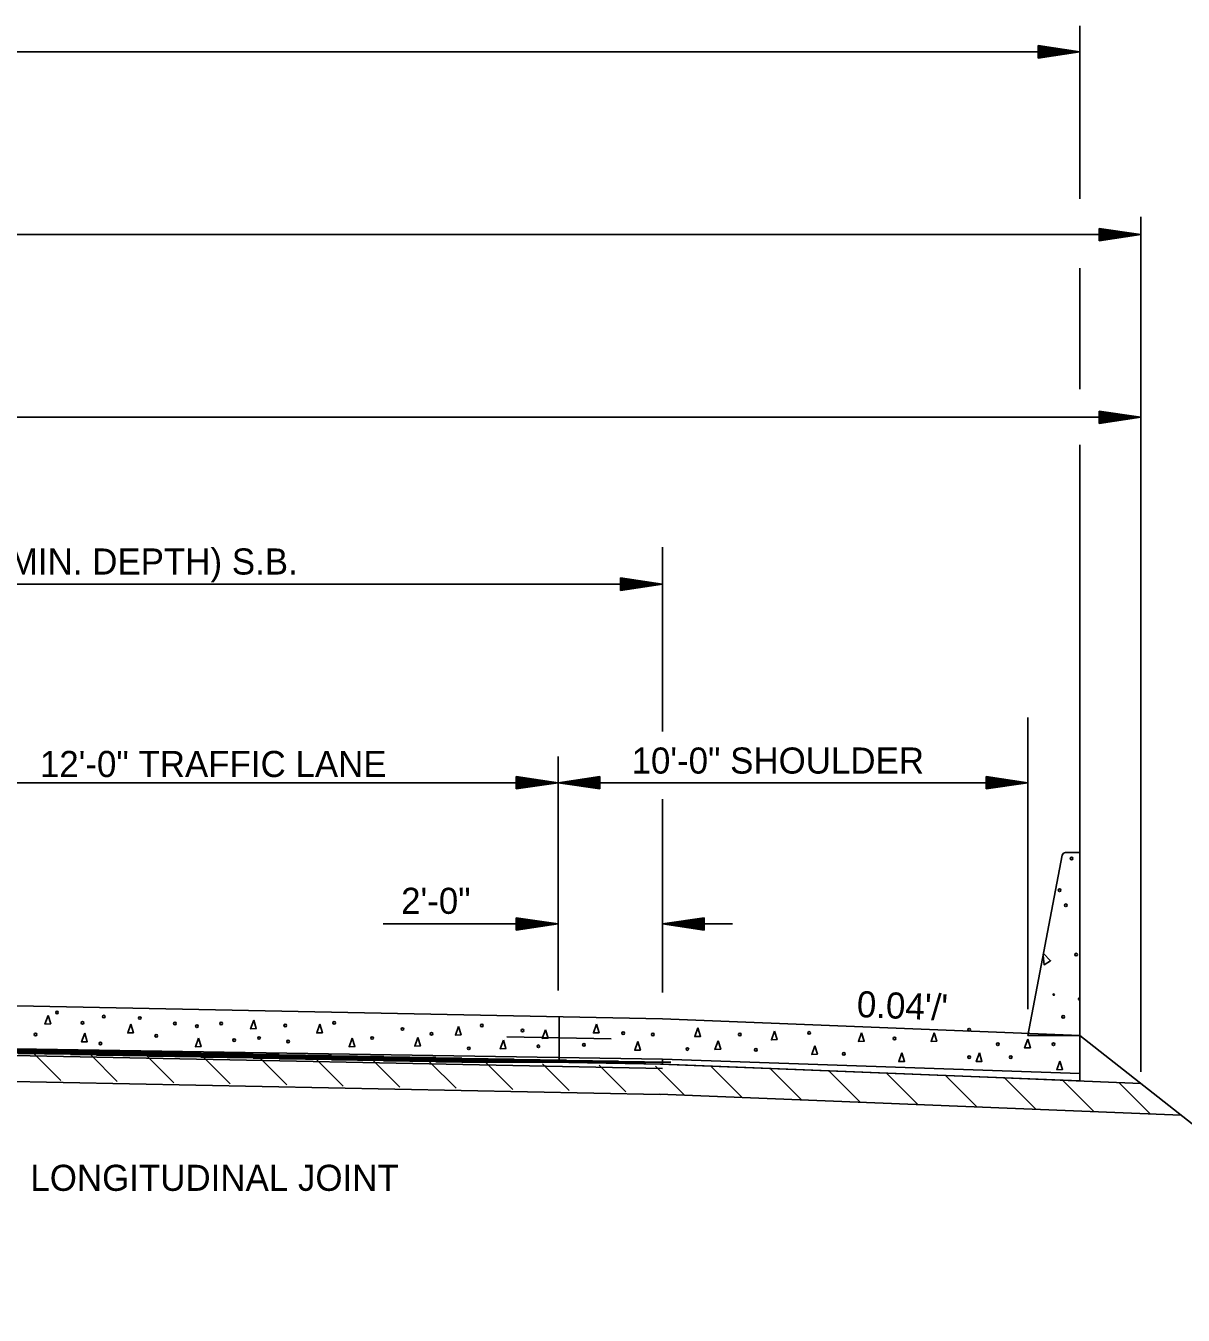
# Model space of a CAD drawing. Extents: x 60325 to 61047, y 53669 to 53767.
# Drawn here: x 60598.35 to 60620.52, y 53687.92 to 53712.62 of the extents above; entities that cross this region are included whole.
import ezdxf

# ---------------------------------------------------------------- set-up
doc = ezdxf.new("R2010")
doc.units = 0
doc.layers.add('R_Border', color=7, linetype='Continuous')
doc.layers.add('R_Border Prem', color=7, linetype='Continuous')

msp = doc.modelspace()

# ---------------------------------------------------------------- linework, layer by layer
at = {"layer": 'R_Border'}
for p, q in [((60610.545, 53699.103), (60610.545, 53702.635)), ((60610.545, 53701.929), (60582.545, 53701.929)), ((60609.745, 53702.049), (60610.545, 53701.929)), ((60609.745, 53702.049), (60609.745, 53701.809)), ((60609.745, 53702.029), (60610.412, 53701.929)), ((60609.745, 53702.009), (60610.274, 53701.929)), ((60609.745, 53701.989), (60610.141, 53701.929)), ((60609.745, 53701.968), (60610.005, 53701.929)), ((60609.745, 53701.948), (60609.872, 53701.929)), ((60609.745, 53701.809), (60610.545, 53701.929)), ((60609.745, 53701.89), (60610.005, 53701.929)), ((60609.745, 53701.85), (60610.274, 53701.929)), ((60609.745, 53701.829), (60610.412, 53701.929)), ((60609.745, 53701.87), (60610.141, 53701.929)), ((60609.745, 53701.911), (60609.872, 53701.929)), ((60608.545, 53694.144), (60608.545, 53698.624)), ((60607.745, 53698.244), (60608.545, 53698.124)), ((60607.745, 53698.244), (60607.745, 53698.004)), ((60607.745, 53698.224), (60608.412, 53698.124)), ((60608.545, 53698.124), (60596.545, 53698.124)), ((60607.745, 53698.204), (60608.274, 53698.124)), ((60607.745, 53698.184), (60608.141, 53698.124)), ((60607.745, 53698.163), (60608.005, 53698.124)), ((60607.745, 53698.143), (60607.872, 53698.124)), ((60607.745, 53698.004), (60608.545, 53698.124)), ((60607.745, 53698.085), (60608.005, 53698.124)), ((60607.745, 53698.045), (60608.274, 53698.124)), ((60607.745, 53698.024), (60608.412, 53698.124)), ((60607.745, 53698.065), (60608.141, 53698.124)), ((60607.745, 53698.106), (60607.872, 53698.124)), ((60610.545, 53694.104), (60610.545, 53697.812)), ((60607.745, 53695.538), (60608.545, 53695.418)), ((60607.745, 53695.298), (60607.745, 53695.538)), ((60607.745, 53695.518), (60608.412, 53695.418)), ((60611.345, 53695.538), (60610.545, 53695.418)), ((60611.345, 53695.518), (60610.679, 53695.418)), ((60611.345, 53695.538), (60611.345, 53695.298)), ((60605.198, 53695.418), (60608.545, 53695.418)), ((60607.745, 53695.498), (60608.274, 53695.418)), ((60607.745, 53695.478), (60608.141, 53695.418)), ((60607.745, 53695.458), (60608.005, 53695.418)), ((60607.745, 53695.437), (60607.872, 53695.418)), ((60607.745, 53695.298), (60608.545, 53695.418)), ((60607.745, 53695.38), (60608.005, 53695.418)), ((60607.745, 53695.339), (60608.274, 53695.418)), ((60607.745, 53695.318), (60608.412, 53695.418)), ((60607.745, 53695.359), (60608.141, 53695.418)), ((60607.745, 53695.4), (60607.872, 53695.418)), ((60610.545, 53695.418), (60611.887, 53695.418)), ((60611.345, 53695.298), (60610.545, 53695.418)), ((60611.345, 53695.318), (60610.679, 53695.418)), ((60611.345, 53695.498), (60610.816, 53695.418)), ((60611.345, 53695.339), (60610.816, 53695.418)), ((60611.345, 53695.478), (60610.95, 53695.418)), ((60611.345, 53695.359), (60610.95, 53695.418)), ((60611.345, 53695.457), (60611.085, 53695.418)), ((60611.345, 53695.379), (60611.085, 53695.418)), ((60611.345, 53695.437), (60611.219, 53695.418)), ((60611.345, 53695.4), (60611.219, 53695.418)), ((60608.564, 53693.655), (60608.564, 53692.822)), ((60607.564, 53693.259), (60608.564, 53693.239)), ((60608.564, 53693.239), (60609.564, 53693.219))]:
    msp.add_line(p, q, dxfattribs=at)
msp.add_lwpolyline([(60582.532, 53694.162), (60584.53, 53694.125), (60610.545, 53693.604)], dxfattribs=at)
at = {"layer": 'R_Border Prem'}
for p, q in [((60618.545, 53709.307), (60618.545, 53712.624)), ((60618.545, 53712.124), (60524.545, 53712.124)), ((60617.745, 53712.244), (60618.545, 53712.124)), ((60617.745, 53712.244), (60617.745, 53712.004)), ((60617.745, 53712.224), (60618.412, 53712.124)), ((60617.745, 53712.204), (60618.274, 53712.124)), ((60617.745, 53712.184), (60618.141, 53712.124)), ((60617.745, 53712.163), (60618.005, 53712.124)), ((60617.745, 53712.143), (60617.872, 53712.124)), ((60617.745, 53712.004), (60618.545, 53712.124)), ((60617.745, 53712.085), (60618.005, 53712.124)), ((60617.745, 53712.045), (60618.274, 53712.124)), ((60617.745, 53712.024), (60618.412, 53712.124)), ((60617.745, 53712.065), (60618.141, 53712.124)), ((60617.745, 53712.106), (60617.872, 53712.124)), ((60619.713, 53696.197), (60619.713, 53708.966)), ((60619.713, 53708.624), (60522.149, 53708.624)), ((60618.913, 53708.744), (60619.713, 53708.624)), ((60618.913, 53708.744), (60618.913, 53708.504)), ((60618.913, 53708.724), (60619.58, 53708.624)), ((60618.913, 53708.704), (60619.442, 53708.624)), ((60618.913, 53708.684), (60619.309, 53708.624)), ((60618.913, 53708.663), (60619.173, 53708.624)), ((60618.913, 53708.643), (60619.04, 53708.624)), ((60618.913, 53708.504), (60619.713, 53708.624)), ((60618.913, 53708.585), (60619.173, 53708.624)), ((60618.913, 53708.545), (60619.442, 53708.624)), ((60618.913, 53708.524), (60619.58, 53708.624)), ((60618.913, 53708.565), (60619.309, 53708.624)), ((60618.913, 53708.606), (60619.04, 53708.624)), ((60618.545, 53705.666), (60618.545, 53707.983)), ((60618.913, 53705.244), (60619.713, 53705.124)), ((60618.913, 53705.244), (60618.913, 53705.004)), ((60618.913, 53705.224), (60619.58, 53705.124)), ((60618.913, 53705.204), (60619.442, 53705.124)), ((60618.913, 53705.184), (60619.309, 53705.124)), ((60618.913, 53705.163), (60619.173, 53705.124)), ((60618.913, 53705.143), (60619.04, 53705.124)), ((60619.713, 53705.124), (60522.149, 53705.124)), ((60618.913, 53705.004), (60619.713, 53705.124)), ((60618.913, 53705.085), (60619.173, 53705.124)), ((60618.913, 53705.045), (60619.442, 53705.124)), ((60618.913, 53705.024), (60619.58, 53705.124)), ((60618.913, 53705.065), (60619.309, 53705.124)), ((60618.913, 53705.106), (60619.04, 53705.124)), ((60618.545, 53696.785), (60618.545, 53704.599)), ((60617.549, 53693.784), (60617.549, 53699.374)), ((60609.345, 53698.244), (60608.545, 53698.124)), ((60609.345, 53698.224), (60608.679, 53698.124)), ((60609.345, 53698.004), (60609.345, 53698.244)), ((60616.749, 53698.244), (60617.549, 53698.124)), ((60616.749, 53698.244), (60616.749, 53698.004)), ((60616.749, 53698.224), (60617.416, 53698.124)), ((60617.549, 53698.124), (60608.545, 53698.124)), ((60609.345, 53698.004), (60608.545, 53698.124)), ((60609.345, 53698.024), (60608.679, 53698.124)), ((60609.345, 53698.204), (60608.816, 53698.124)), ((60609.345, 53698.045), (60608.816, 53698.124)), ((60609.345, 53698.184), (60608.95, 53698.124)), ((60609.345, 53698.065), (60608.95, 53698.124)), ((60609.345, 53698.164), (60609.085, 53698.124)), ((60609.345, 53698.086), (60609.085, 53698.124)), ((60609.345, 53698.143), (60609.219, 53698.124)), ((60609.345, 53698.106), (60609.219, 53698.124)), ((60616.749, 53698.204), (60617.278, 53698.124)), ((60616.749, 53698.184), (60617.145, 53698.124)), ((60616.749, 53698.163), (60617.009, 53698.124)), ((60616.749, 53698.143), (60616.876, 53698.124)), ((60616.749, 53698.004), (60617.549, 53698.124)), ((60616.749, 53698.085), (60617.009, 53698.124)), ((60616.749, 53698.045), (60617.278, 53698.124)), ((60616.749, 53698.024), (60617.416, 53698.124)), ((60616.749, 53698.065), (60617.145, 53698.124)), ((60616.749, 53698.106), (60616.876, 53698.124)), ((60618.208, 53696.738), (60617.549, 53693.284)), ((60618.546, 53696.785), (60618.268, 53696.785)), ((60618.545, 53693.284), (60618.546, 53696.785)), ((60619.713, 53692.586), (60619.713, 53696.197)), ((60618.545, 53693.784), (60618.545, 53692.411)), ((60610.545, 53693.604), (60618.545, 53693.284)), ((60571.545, 53693.511), (60610.545, 53692.731)), ((60571.545, 53693.431), (60610.545, 53692.651)), ((60617.549, 53693.284), (60618.545, 53693.284)), ((60618.545, 53693.284), (60625.351, 53687.924)), ((60571.545, 53692.931), (60610.502, 53692.152)), ((60594.704, 53693.008), (60598.705, 53693.008)), ((60595.204, 53692.998), (60599.205, 53692.998)), ((60595.704, 53692.988), (60599.705, 53692.988)), ((60596.204, 53692.978), (60600.205, 53692.978)), ((60596.704, 53692.968), (60600.705, 53692.968)), ((60597.204, 53692.958), (60601.205, 53692.958)), ((60597.704, 53692.948), (60601.705, 53692.948)), ((60598.204, 53692.938), (60602.205, 53692.938)), ((60598.508, 53692.932), (60599.019, 53692.421)), ((60598.704, 53692.928), (60602.705, 53692.928)), ((60599.204, 53692.918), (60603.205, 53692.918)), ((60599.591, 53692.91), (60600.101, 53692.4)), ((60599.704, 53692.908), (60603.705, 53692.908)), ((60600.204, 53692.898), (60604.205, 53692.898)), ((60600.673, 53692.888), (60601.183, 53692.378)), ((60600.704, 53692.888), (60604.705, 53692.888)), ((60601.204, 53692.878), (60605.205, 53692.878)), ((60601.704, 53692.868), (60605.705, 53692.868)), ((60601.755, 53692.867), (60602.266, 53692.356)), ((60602.204, 53692.858), (60606.205, 53692.858)), ((60602.704, 53692.848), (60606.705, 53692.848)), ((60602.838, 53692.845), (60603.348, 53692.335)), ((60603.204, 53692.838), (60607.205, 53692.838)), ((60603.704, 53692.828), (60607.705, 53692.828)), ((60603.92, 53692.823), (60604.43, 53692.313)), ((60604.204, 53692.818), (60608.205, 53692.818)), ((60604.704, 53692.808), (60608.705, 53692.808)), ((60605.002, 53692.802), (60605.513, 53692.292)), ((60605.204, 53692.798), (60609.205, 53692.798)), ((60605.704, 53692.788), (60609.705, 53692.788)), ((60606.085, 53692.78), (60606.595, 53692.27)), ((60606.204, 53692.778), (60610.205, 53692.778)), ((60606.704, 53692.768), (60610.705, 53692.768)), ((60607.167, 53692.759), (60607.677, 53692.248)), ((60608.249, 53692.737), (60608.759, 53692.227)), ((60609.331, 53692.715), (60609.842, 53692.205)), ((60610.414, 53692.694), (60610.97, 53692.137)), ((60610.51, 53692.732), (60618.545, 53692.411)), ((60611.474, 53692.694), (60612.075, 53692.093)), ((60612.613, 53692.648), (60613.213, 53692.048)), ((60613.735, 53692.603), (60614.336, 53692.003)), ((60614.838, 53692.559), (60615.438, 53691.959)), ((60615.968, 53692.514), (60616.568, 53691.914)), ((60617.078, 53692.47), (60619.713, 53692.364)), ((60617.098, 53692.469), (60617.698, 53691.868)), ((60618.21, 53692.424), (60618.811, 53691.824)), ((60619.293, 53692.381), (60619.894, 53691.781)), ((60610.487, 53692.157), (60620.484, 53691.757))]:
    msp.add_line(p, q, dxfattribs=at)
for points in [[(60617.841, 53694.813), (60617.858, 53694.636), (60617.983, 53694.714), (60617.848, 53694.85)], [(60598.776, 53693.668), (60598.715, 53693.502), (60598.825, 53693.506), (60598.776, 53693.668)], [(60602.714, 53693.575), (60602.653, 53693.409), (60602.763, 53693.414), (60602.714, 53693.575)], [(60599.476, 53693.324), (60599.416, 53693.158), (60599.526, 53693.163), (60599.476, 53693.324)], [(60600.362, 53693.496), (60600.301, 53693.33), (60600.411, 53693.334), (60600.362, 53693.496)], [(60603.983, 53693.496), (60603.922, 53693.33), (60604.032, 53693.334), (60603.983, 53693.496)], [(60606.639, 53693.456), (60606.579, 53693.29), (60606.689, 53693.295), (60606.639, 53693.456)], [(60608.304, 53693.39), (60608.244, 53693.224), (60608.354, 53693.229), (60608.304, 53693.39)], [(60609.282, 53693.496), (60609.222, 53693.33), (60609.332, 53693.334), (60609.282, 53693.496)], [(60611.227, 53693.426), (60611.166, 53693.26), (60611.276, 53693.265), (60611.227, 53693.426)], [(60612.694, 53693.364), (60612.634, 53693.198), (60612.744, 53693.203), (60612.694, 53693.364)], [(60614.363, 53693.333), (60614.302, 53693.167), (60614.412, 53693.172), (60614.363, 53693.333)], [(60615.753, 53693.333), (60615.693, 53693.167), (60615.803, 53693.172), (60615.753, 53693.333)], [(60601.657, 53693.232), (60601.596, 53693.066), (60601.706, 53693.07), (60601.657, 53693.232)], [(60604.604, 53693.232), (60604.543, 53693.066), (60604.653, 53693.07), (60604.604, 53693.232)], [(60605.859, 53693.245), (60605.799, 53693.079), (60605.909, 53693.083), (60605.859, 53693.245)], [(60607.498, 53693.192), (60607.438, 53693.026), (60607.548, 53693.03), (60607.498, 53693.192)], [(60610.075, 53693.166), (60610.015, 53693), (60610.125, 53693.004), (60610.075, 53693.166)], [(60611.613, 53693.179), (60611.552, 53693.013), (60611.662, 53693.017), (60611.613, 53693.179)], [(60613.467, 53693.086), (60613.406, 53692.92), (60613.516, 53692.925), (60613.467, 53693.086)], [(60617.545, 53693.21), (60617.485, 53693.044), (60617.595, 53693.048), (60617.545, 53693.21)], [(60615.135, 53692.947), (60615.075, 53692.781), (60615.185, 53692.786), (60615.135, 53692.947)], [(60616.618, 53692.947), (60616.558, 53692.781), (60616.668, 53692.786), (60616.618, 53692.947)], [(60618.163, 53692.792), (60618.103, 53692.626), (60618.213, 53692.631), (60618.163, 53692.792)]]:
    msp.add_lwpolyline(points, dxfattribs=at)
for points in [[(60596.541, 53692.979), (60596.545, 53693.051), (60610.545, 53692.826), (60610.545, 53692.731)], [(60610.545, 53692.731), (60610.545, 53692.826), (60618.545, 53692.551), (60618.545, 53692.411)]]:
    msp.add_lwpolyline(points, close=True, dxfattribs=at)
for centre, radius in [((60618.386, 53696.674), 0.0254), ((60618.156, 53696.065), 0.0254), ((60618.277, 53695.776), 0.0254), ((60618.472, 53694.831), 0.0254), ((60618.044, 53694.066), 0.0127), ((60598.945, 53693.723), 0.025), ((60599.434, 53693.525), 0.025), ((60599.843, 53693.644), 0.025), ((60600.531, 53693.617), 0.025), ((60601.205, 53693.512), 0.025), ((60602.09, 53693.512), 0.025), ((60604.257, 53693.525), 0.025), ((60618.226, 53693.639), 0.0254), ((60598.535, 53693.3), 0.025), ((60600.848, 53693.274), 0.025), ((60601.627, 53693.459), 0.025), ((60603.319, 53693.472), 0.025), ((60605.566, 53693.406), 0.025), ((60606.121, 53693.313), 0.025), ((60607.086, 53693.472), 0.025), ((60607.865, 53693.379), 0.025), ((60609.795, 53693.327), 0.025), ((60610.363, 53693.3), 0.025), ((60612.028, 53693.3), 0.025), ((60613.357, 53693.331), 0.025), ((60616.422, 53693.392), 0.025), ((60599.777, 53693.128), 0.025), ((60602.341, 53693.194), 0.025), ((60602.817, 53693.234), 0.025), ((60603.372, 53693.168), 0.025), ((60604.984, 53693.234), 0.025), ((60606.835, 53693.036), 0.025), ((60608.169, 53693.075), 0.025), ((60609.042, 53693.102), 0.025), ((60611.024, 53693.022), 0.025), ((60612.337, 53693.007), 0.025), ((60614.994, 53693.223), 0.025), ((60616.972, 53693.115), 0.025), ((60618.038, 53693.115), 0.025), ((60614.021, 53692.929), 0.025), ((60616.422, 53692.867), 0.025), ((60617.219, 53692.867), 0.025)]:
    msp.add_circle(centre, radius, dxfattribs=at)
msp.add_arc((60618.543, 53693.981), 0.0254, 84.1587, 275.8249, dxfattribs=at)
msp.add_ellipse((60618.268, 53696.724), major_axis=(0, 0.0619), ratio=0.9997, start_param=0, end_param=1.380698, dxfattribs=at)

# ---------------------------------------------------------------- texts
at = {"layer": 'R_Border'}
for s, p in [('28\'-0" DIAMOND GRINDING (1/8" MIN. DEPTH) S.B.', (60587.687, 53702.112)), ('12\'-0" TRAFFIC LANE', (60598.617, 53698.233)), ('2\'-0"', (60605.539, 53695.612)), ('LONGITUDINAL JOINT', (60598.435, 53690.306))]:
    msp.add_text(s, height=0.5, dxfattribs=at).set_placement(p)
at = {"layer": 'R_Border Prem'}
msp.add_text('10\'-0" SHOULDER', height=0.5, dxfattribs=at).set_placement((60609.954, 53698.299))
msp.add_text("0.04'/'", height=0.5, rotation=357.7094, dxfattribs=at).set_placement((60614.263, 53693.636))

doc.saveas('drawing.dxf')
